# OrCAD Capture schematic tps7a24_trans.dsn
size A; title: TPS7A24 200-mA, 18-V, ultra-low-IQ, low-dropout; rev: 1.0; note: SBVS386 - OCTOBER 2019
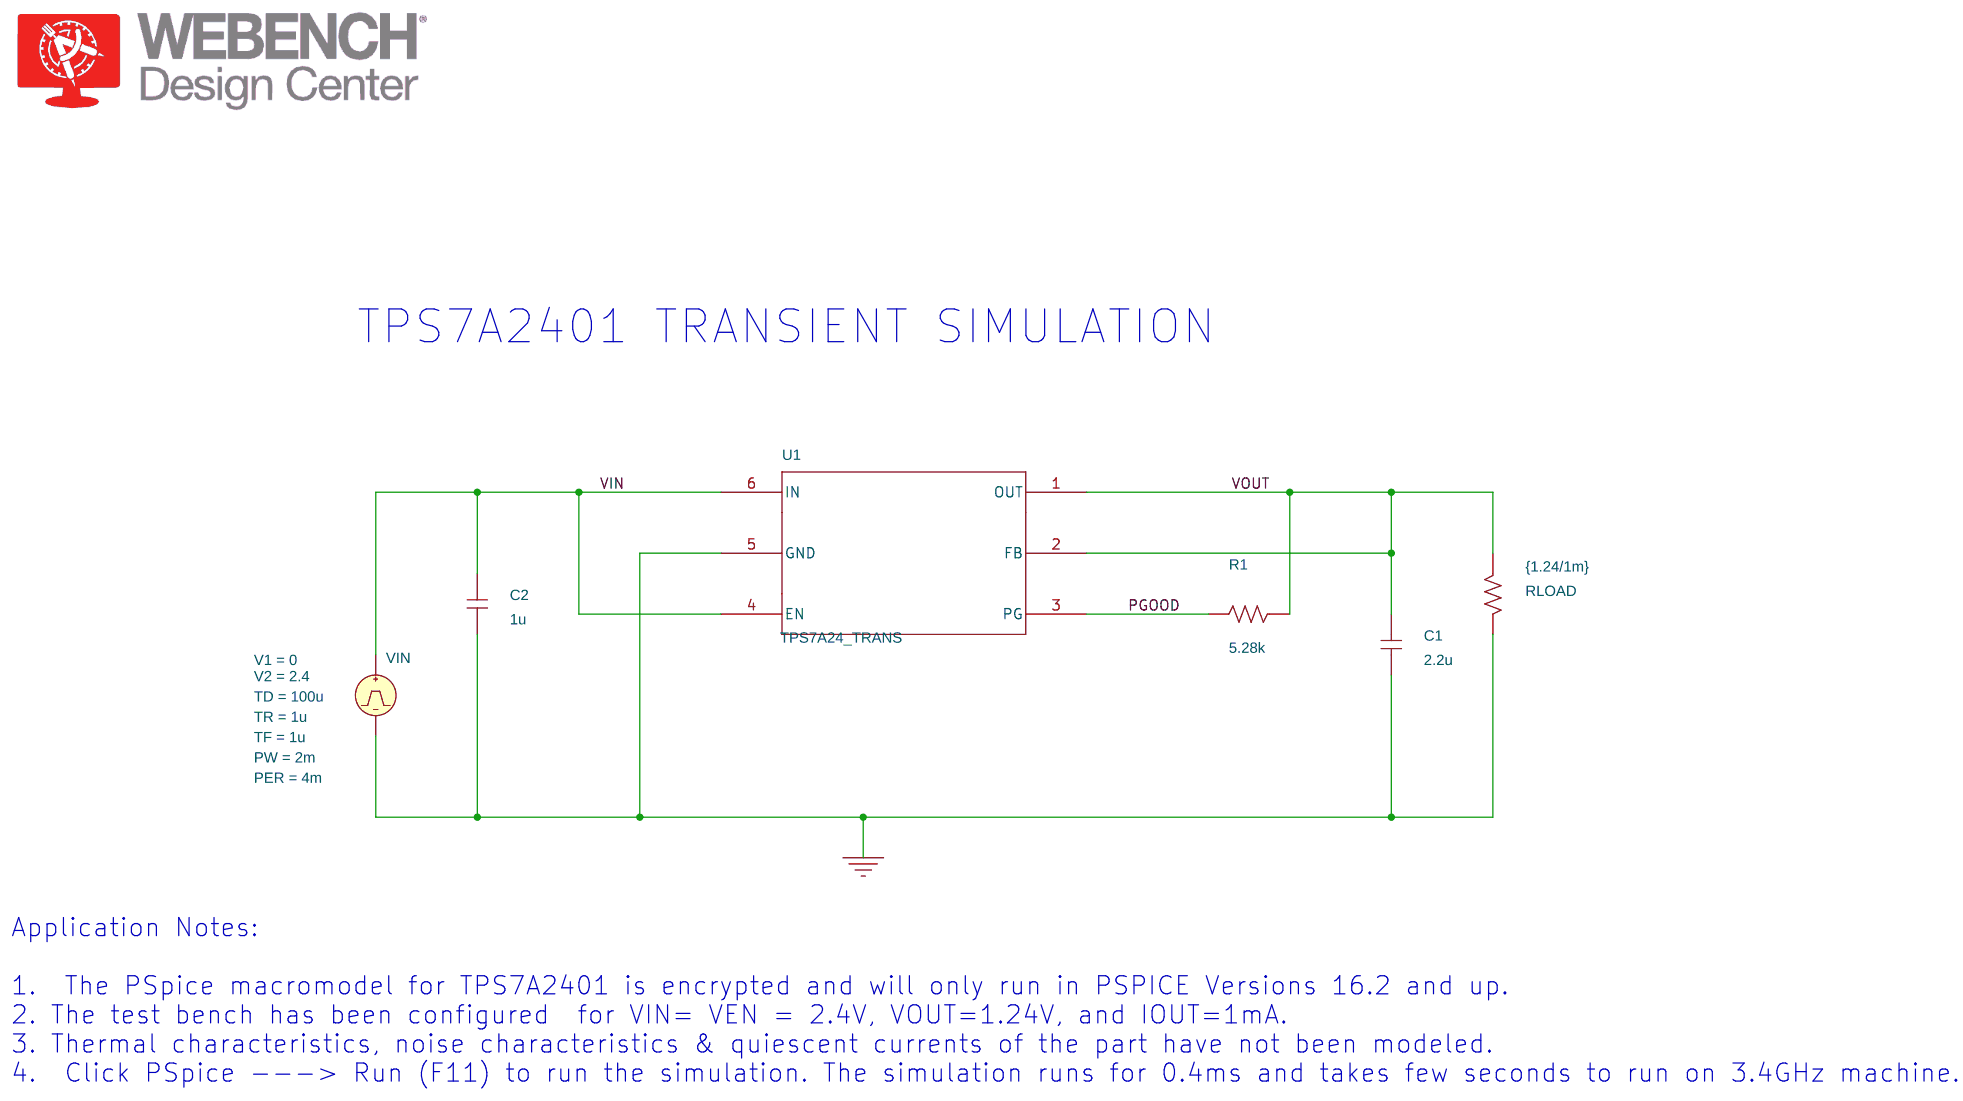
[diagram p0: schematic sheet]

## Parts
C1  2.2u  [RAD/CK05]
C2  1u  [RAD/CK05]
R1  5.28k  [AX/RC05]
RLOAD  {1.24/1m}  [AX/RC05]
U1  TPS7A24_TRANS
VIN  VPULSE

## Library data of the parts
C1 C2 = C
R1 RLOAD = R
U1 = TPS7A24_TRANS
VIN = VPULSE: PER: 4m; PW: 2m; TD: 100u; TF: 1u; TR: 1u; V1: 0; V2: 2.4

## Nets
VIN: C2.2 U1.4(EN) U1.6(IN) VIN.1(+)
0: C1.1 C2.1 RLOAD.2 U1.5(GND) VIN.2(-)
PGOOD: R1.2 U1.3(PG)
VOUT: C1.2 R1.1 RLOAD.1 U1.1(OUT) U1.2(FB)

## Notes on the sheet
- TPS7A2401 TRANSIENT SIMULATION
- Application Notes:
  1.  The PSpice macromodel for TPS7A2401 is encrypted and will only run in PSPICE Versions 16.2 and up.
  2. The test bench has been configured  for VIN= VEN = 2.4V, VOUT=1.24V, and IOUT=1mA.
  3. Thermal characteristics, noise characteristics & quiescent currents of the part have not been modeled.
  4.  Click PSpice ---> Run (F11) to run the simulation. The simulation runs for 0.4ms and takes few seconds to run on 3.4GHz machine.
